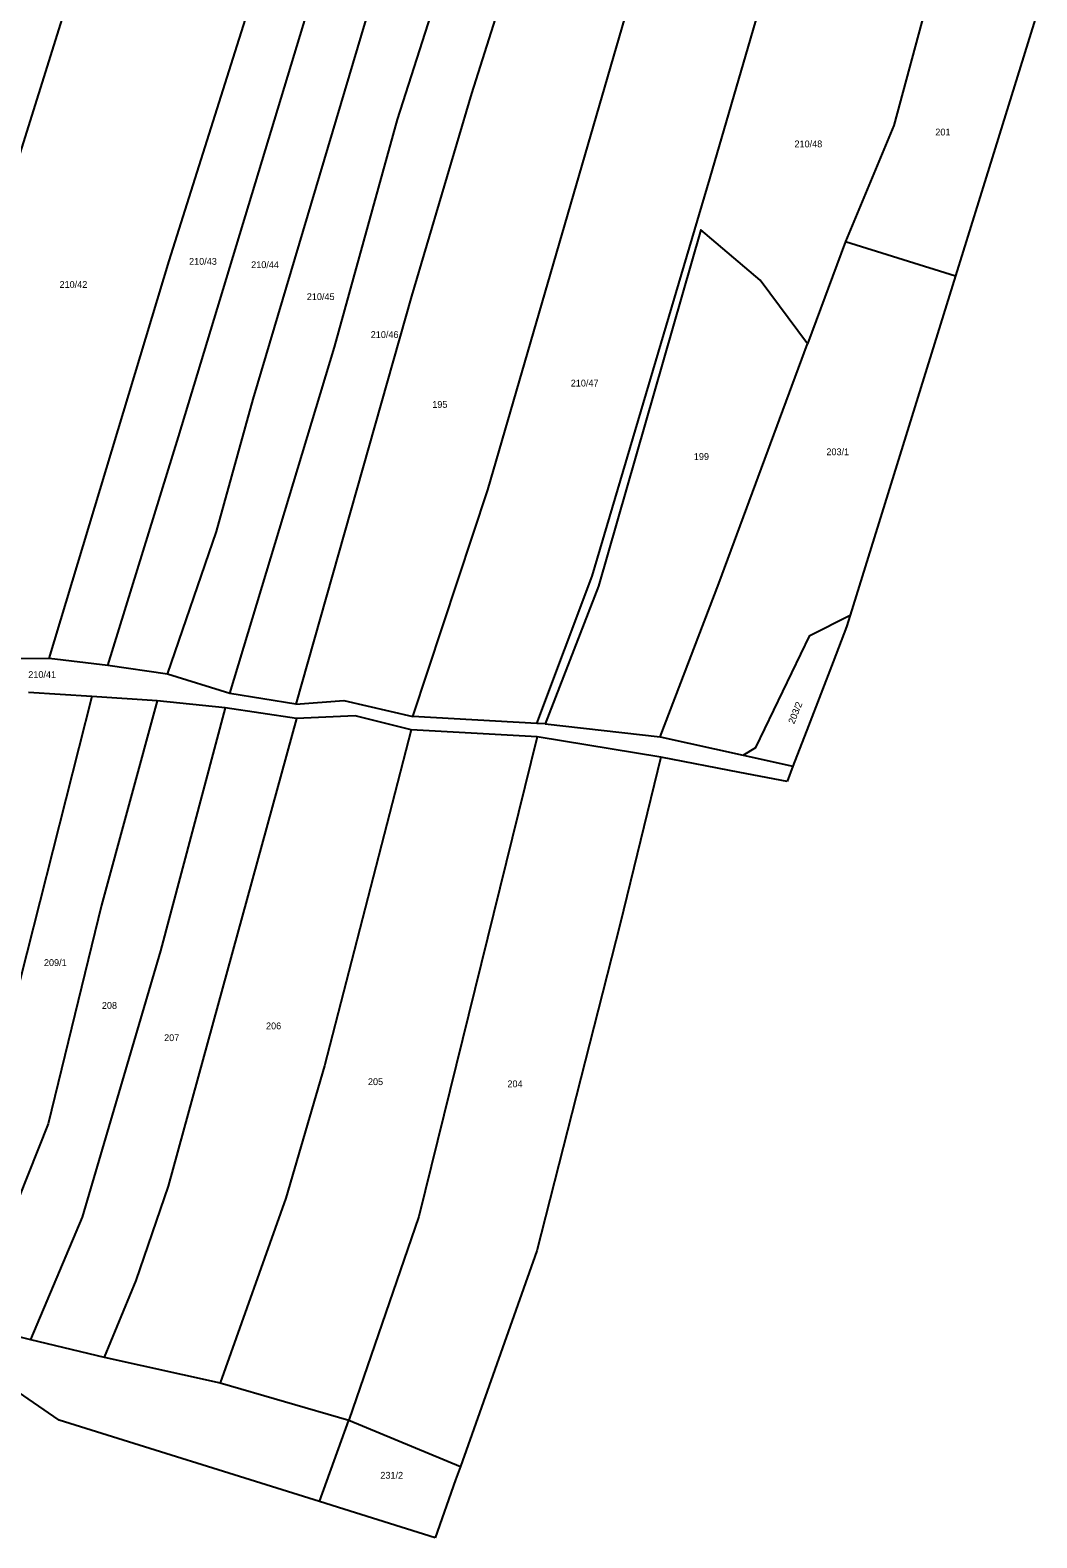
# Model space of a CAD drawing. Extents: x -744566 to -741843, y -1128407 to -1126744.
# Drawn here: x -742498.8 to -742246.8, y -1127907.2 to -1127529.8 of the extents above; entities that cross this region are included whole.
import ezdxf

# ---------------------------------------------------------------- set-up
doc = ezdxf.new("R2010")
doc.units = 0
doc.layers.add('Hranice parcel', color=7, linetype='Continuous')
doc.layers.add('Parcelní čísla', color=7, linetype='Continuous')

msp = doc.modelspace()

# ---------------------------------------------------------------- linework, layer by layer
at = {"layer": 'Hranice parcel'}
for p, q in [((-742246.84, -1127525.71), (-742259.53, -1127566.57)), ((-742259.53, -1127566.57), (-742267.21, -1127591.32)), ((-742294.71, -1127582.66), (-742304.21, -1127608.28)), ((-742294.71, -1127582.66), (-742267.21, -1127591.32)), ((-742267.21, -1127591.32), (-742293.55, -1127676.19)), ((-742293.55, -1127676.19), (-742294.48, -1127679.19)), ((-742294.48, -1127679.19), (-742297.82, -1127687.89)), ((-742494, -1127687.08), (-742539.98, -1127687.22)), ((-742479.32, -1127688.85), (-742494, -1127687.08)), ((-742297.82, -1127687.89), (-742304, -1127703.97)), ((-742464.41, -1127690.97), (-742479.32, -1127688.85)), ((-742448.8, -1127695.84), (-742464.41, -1127690.97)), ((-742483.38, -1127696.63), (-742499.23, -1127695.56)), ((-742467.04, -1127697.67), (-742483.38, -1127696.63)), ((-742449.94, -1127699.44), (-742467.04, -1127697.67)), ((-742432.3, -1127698.48), (-742448.8, -1127695.84)), ((-742432.12, -1127702.08), (-742449.94, -1127699.44)), ((-742372.01, -1127703.32), (-742403.02, -1127701.6)), ((-742371.88, -1127706.65), (-742403.42, -1127704.93)), ((-742369.9, -1127703.45), (-742372.01, -1127703.32)), ((-742340.92, -1127711.81), (-742371.88, -1127706.65)), ((-742369.9, -1127703.45), (-742341.09, -1127706.66)), ((-742341.09, -1127706.66), (-742320.38, -1127711.26)), ((-742304, -1127703.97), (-742307.87, -1127714.04)), ((-742321.14, -1127715.58), (-742340.92, -1127711.81)), ((-742320.38, -1127711.26), (-742307.87, -1127714.04)), ((-742307.87, -1127714.04), (-742309.33, -1127717.84)), ((-742309.33, -1127717.84), (-742321.14, -1127715.58)), ((-742498.72, -1127857.52), (-742480.24, -1127862.01)), ((-742480.24, -1127862.01), (-742451.26, -1127868.39)), ((-742451.26, -1127868.39), (-742419.07, -1127877.77)), ((-742491.5, -1127877.75), (-742503.01, -1127869.85)), ((-742426.38, -1127898.15), (-742491.5, -1127877.75)), ((-742426.38, -1127898.15), (-742419.07, -1127877.77)), ((-742419.07, -1127877.77), (-742391.12, -1127889.33)), ((-742391.12, -1127889.33), (-742392.3, -1127892.65)), ((-742392.3, -1127892.65), (-742397.46, -1127907.21)), ((-742420.31, -1127900.05), (-742426.38, -1127898.15)), ((-742397.46, -1127907.21), (-742420.31, -1127900.05))]:
    msp.add_line(p, q, dxfattribs=at)
for points in [[(-742539.98, -1127687.22), (-742509.38, -1127586.29), (-742471.63, -1127465.86)], [(-742494, -1127687.08), (-742463.97, -1127587.54), (-742428.89, -1127476.24)], [(-742479.32, -1127688.85), (-742461.68, -1127631.58), (-742415.87, -1127480.36)], [(-742464.41, -1127690.97), (-742452.19, -1127655.25), (-742442.95, -1127622.18), (-742402.15, -1127485.01)], [(-742448.8, -1127695.84), (-742422.61, -1127609.18), (-742406.86, -1127552.13), (-742387.37, -1127491.14)], [(-742373.12, -1127497.63), (-742388.36, -1127545.64), (-742403.33, -1127596.39), (-742432.3, -1127698.48)], [(-742403.02, -1127701.6), (-742384.25, -1127644.88), (-742343.44, -1127504.37)], [(-742372.01, -1127703.32), (-742358.1, -1127666.45), (-742328.66, -1127567.04), (-742312.99, -1127513.08), (-742313.1, -1127510.34)], [(-742274.2, -1127522.4), (-742282.6, -1127553.63), (-742294.71, -1127582.66)], [(-742304.21, -1127608.28), (-742316.12, -1127592.36), (-742330.9, -1127579.81), (-742356.55, -1127668.96), (-742369.9, -1127703.45)], [(-742341.09, -1127706.66), (-742326.47, -1127668.34), (-742304.21, -1127608.28)], [(-742320.38, -1127711.26), (-742317.14, -1127709.37), (-742303.66, -1127681.35), (-742293.55, -1127676.19)], [(-742483.38, -1127696.63), (-742499.62, -1127760.84), (-742511.87, -1127809.1), (-742521.5, -1127833.81), (-742527.8, -1127847.44)], [(-742467.04, -1127697.67), (-742480.9, -1127748.82), (-742494.32, -1127803.6), (-742511.96, -1127847.84)], [(-742432.3, -1127698.48), (-742420.3, -1127697.56), (-742403.02, -1127701.6)], [(-742449.94, -1127699.44), (-742466.13, -1127760.26), (-742485.77, -1127826.93), (-742498.72, -1127857.52)], [(-742432.12, -1127702.08), (-742464.27, -1127819.17), (-742472.32, -1127842.8), (-742480.24, -1127862.01)], [(-742403.42, -1127704.93), (-742417.48, -1127701.42), (-742432.12, -1127702.08)], [(-742403.42, -1127704.93), (-742425.12, -1127789.08), (-742434.82, -1127822.21), (-742451.26, -1127868.39)], [(-742371.88, -1127706.65), (-742401.48, -1127826.73), (-742419.07, -1127877.77)], [(-742340.92, -1127711.81), (-742351.14, -1127753.54), (-742371.99, -1127835.4), (-742391.12, -1127889.33)], [(-742511.96, -1127847.84), (-742513.81, -1127853.78), (-742498.72, -1127857.52)]]:
    msp.add_lwpolyline(points, dxfattribs=at)

# ---------------------------------------------------------------- texts
at = {"layer": 'Parcelní čísla'}
for s, p in [('201', (-742272.25, -1127556.14)), ('210/48', (-742307.5, -1127559.11)), ('210/43', (-742459.02, -1127588.52)), ('210/44', (-742443.47, -1127589.35)), ('210/42', (-742491.44, -1127594.3)), ('210/45', (-742429.55, -1127597.35)), ('210/46', (-742413.55, -1127606.84)), ('210/47', (-742363.49, -1127618.99)), ('195', (-742398.15, -1127624.33)), ('203/1', (-742299.51, -1127636.19)), ('199', (-742332.68, -1127637.37)), ('210/41', (-742499.26, -1127691.95)), ('209/1', (-742495.34, -1127764.05)), ('208', (-742480.84, -1127774.79)), ('206', (-742439.75, -1127779.9)), ('207', (-742465.26, -1127782.86)), ('205', (-742414.25, -1127793.87)), ('204', (-742379.34, -1127794.41)), ('231/2', (-742411.14, -1127892.4))]:
    msp.add_text(s, height=1.7, dxfattribs=at).set_placement(p)
msp.add_text('203/2', height=1.7, rotation=68, dxfattribs=at).set_placement((-742307.581, -1127703.618))

doc.saveas('drawing.dxf')
